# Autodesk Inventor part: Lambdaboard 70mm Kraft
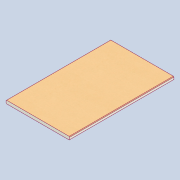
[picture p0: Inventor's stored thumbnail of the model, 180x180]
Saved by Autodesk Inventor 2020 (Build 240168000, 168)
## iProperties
Created: 2020-11
Part Number: Lambdaboard 70mm Kraft
Material: Polyisocyanurate
Document SubType Name: Modeling
Designer: Yolande
Density: 0.032 g/cm^3
Appearance: Pink
Author: Yolande
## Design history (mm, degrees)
sketch "Sketch1"
  geometry: L1 (10, 0)-(1210, 0); L2 (1220, 10)-(1220, 50); L3 (1210, 60)-(10, 60); L4 (0, 50)-(0, 10); A1 r 10 centre (10, 50) between (10, 60) and (0, 50); A2 r 10 centre (10, 10) between (0, 10) and (10, 0); A3 r 10 centre (1210, 50) between (1220, 50) and (1210, 60); A4 r 10 centre (1210, 10) between (1210, 0) and (1220, 10); 3 further points
  constraints: 8 end point, 8 point on circle, 8 tangent, 6 point on line, 4 centre point, 3 equal radius, 3 perpendicular, 1 horizontal
  dimensions: "d0" = 1220 distance of point (0, 0) point (1220, 0); "d1" = 60 distance of point (1220, 0) point (1220, 60); "d2" = 10 radius of A1
extrude "Extrusion1" new body sketch "Sketch1" distance "d3" = 2000; taper "d4" = 0 deg
body "Solid1"
